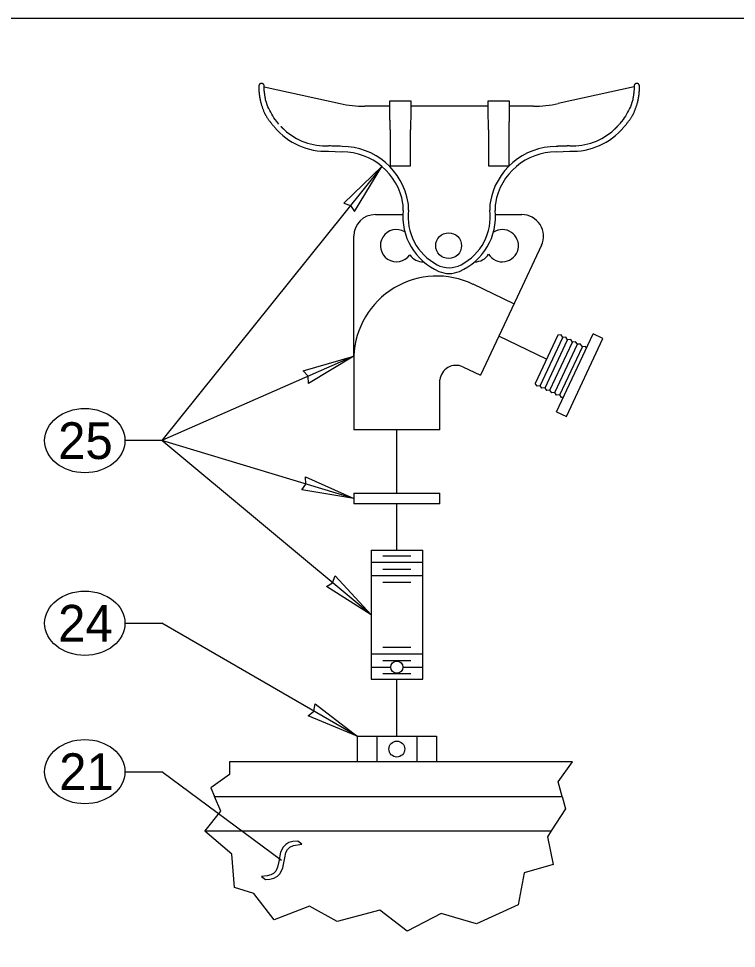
# Model space of a CAD drawing. Extents: x 99862 to 104211, y 98939 to 102076.
# Drawn here: x 100530.8 to 100843.6, y 101670.5 to 102075.5 of the extents above; entities that cross this region are included whole.
import ezdxf

# ---------------------------------------------------------------- set-up
doc = ezdxf.new("R2010")
doc.units = 0
for name, color, linetype in [('Level 1', 7, 'Continuous'), ('Level 15', 7, 'Continuous'), ('Level 17', 7, 'Continuous'), ('Level 18', 7, 'Continuous'), ('Level 2', 7, 'Continuous'), ('Level 20', 7, 'Continuous'), ('Level 22', 7, 'Continuous'), ('Level 25', 7, 'Continuous'), ('Level 26', 7, 'Continuous'), ('Level 27', 7, 'Continuous')]:
    doc.layers.add(name, color=color, linetype=linetype)

msp = doc.modelspace()

# ---------------------------------------------------------------- linework, layer by layer
at = {"layer": 'Level 1'}
msp.add_lwpolyline([(99862, 99999.5), (103151, 99999.5), (103151, 102075.5), (99862, 102075.5)], close=True, dxfattribs=at)
at = {"layer": 'Level 15'}
for p, q in [((100637.87, 102045.83), (100670.91, 102038.49)), ((100799.04, 102045.83), (100766.01, 102038.49)), ((100689.17, 102011.09), (100593.19, 101891.68)), ((100760.94, 101927.13), (100740.1, 101937.17)), ((100676.92, 101928.49), (100593.19, 101891.68)), ((100695.68, 101868.81), (100695.67, 101896.36)), ((100593.19, 101891.68), (100577.19, 101891.68)), ((100684.42, 101815.87), (100593.19, 101891.68)), ((100676.92, 101866.47), (100593.19, 101891.68)), ((100695.69, 101844), (100695.68, 101864.12)), ((100577.19, 101812.14), (100593.19, 101812.14)), ((100678.35, 101762.98), (100593.19, 101812.14)), ((100695.73, 101762.98), (100695.72, 101787.75)), ((100577.19, 101747.5), (100593.19, 101747.5)), ((100645.46, 101708.87), (100593.19, 101747.5)), ((100650.38, 101717.06), (100648.66, 101716.6)), ((100652.52, 101717.18), (100650.38, 101717.06)), ((100654.22, 101715.92), (100652.52, 101717.18)), ((100646.11, 101714.59), (100644.96, 101712.41)), ((100647.26, 101715.8), (100646.11, 101714.59)), ((100648.66, 101716.6), (100647.26, 101715.8)), ((100647.36, 101712.33), (100648.05, 101713.66)), ((100648.05, 101713.66), (100649.08, 101714.64)), ((100649.08, 101714.64), (100650.57, 101715.34)), ((100650.57, 101715.34), (100654.22, 101715.92)), ((100644.96, 101712.41), (100644.24, 101708.38)), ((100646.02, 101705.62), (100646.89, 101709.95)), ((100646.89, 101709.95), (100647.36, 101712.33)), ((100643.73, 101705.89), (100642.9, 101704.16)), ((100644.24, 101708.38), (100643.73, 101705.89)), ((100644.81, 101703.19), (100646.02, 101705.62)), ((100639.1, 101702.09), (100636.69, 101701.85)), ((100636.69, 101701.85), (100638.39, 101700.59)), ((100638.39, 101700.59), (100640.38, 101700.62)), ((100640.78, 101702.53), (100639.1, 101702.09)), ((100640.38, 101700.62), (100642.11, 101701.06)), ((100641.96, 101703.2), (100640.78, 101702.53)), ((100642.9, 101704.16), (100641.96, 101703.2)), ((100642.11, 101701.06), (100643.59, 101701.92)), ((100643.59, 101701.92), (100644.81, 101703.19))]:
    msp.add_line(p, q, dxfattribs=at)
for points in [[(100689.17, 102011.09), (100672.54, 101995.17), (100675.53, 101994.12), (100677.19, 101991.43)], [(100676.92, 101928.49), (100657.22, 101916.57), (100656.99, 101919.73), (100654.82, 101922.04)], [(100676.92, 101866.47), (100654.2, 101870.19), (100656.07, 101872.74), (100655.92, 101875.91)], [(100684.42, 101815.87), (100664.96, 101828.17), (100667.68, 101829.79), (100668.77, 101832.76)], [(100678.35, 101762.98), (100657.09, 101771.81), (100659.5, 101773.86), (100660.07, 101776.98)]]:
    msp.add_lwpolyline(points, close=True, dxfattribs=at)
for centre, start, end in [((100681.76, 102087.3), 257.4712, 270), ((100755.16, 102087.3), 270, 282.5288)]:
    msp.add_arc(centre, 50, start, end, dxfattribs=at)
at = {"layer": 'Level 17'}
for p, q in [((100635.53, 102046.09), (100635.53, 102044.84)), ((100637.87, 102044.84), (100637.87, 102046.09)), ((100799.04, 102046.09), (100799.04, 102044.84)), ((100801.39, 102044.84), (100801.39, 102046.09)), ((100665.92, 102017.72), (100671.76, 102017.51)), ((100765.16, 102017.51), (100770.98, 102017.72))]:
    msp.add_line(p, q, dxfattribs=at)
for centre, radius, start, end in [((100772.09, 102047), 26.95, 317.1843, 319.798), ((100664.84, 102047.03), 29.33, 220.0203, 272.1185), ((100664.82, 102047), 26.97, 227.4639, 272.2359), ((100772.09, 102047), 29.3, 267.8348, 319.9497), ((100772.09, 102047), 26.97, 267.7641, 312.5361), ((100671.71, 101990.56), 29.28, 9.1878, 89.8248), ((100671.71, 101990.56), 26.95, 9.4424, 89.8097), ((100765.2, 101990.56), 29.28, 90.1752, 170.8122), ((100765.2, 101990.56), 26.95, 90.1903, 170.5576), ((100687.2, 101993.13), 11.25, 354.1689, 9.4424), ((100724.32, 101989.34), 23.79, 173.2924, 242.1551), ((100689.51, 101993.44), 11.25, 353.2924, 9.1878), ((100712.6, 101989.34), 23.79, 297.8449, 6.7076), ((100747.4, 101993.44), 11.25, 170.8122, 186.7076), ((100749.71, 101993.13), 11.25, 170.5576, 185.8311), ((100724.32, 101989.34), 26.06, 174.1689, 246.6908), ((100712.6, 101989.34), 26.06, 293.3092, 5.8311), ((100718.46, 101978.25), 11.25, 242.1551, 297.8449), ((100718.46, 101975.74), 11.25, 246.6908, 293.3092)]:
    msp.add_arc(centre, radius, start, end, dxfattribs=at)
for points, degree in [([(100637.87, 102046.09), (100637.87, 102046.13), (100637.87, 102046.17), (100637.87, 102046.2), (100637.85, 102046.33), (100637.82, 102046.46), (100637.76, 102046.58), (100637.71, 102046.7), (100637.63, 102046.81), (100637.54, 102046.91), (100637.45, 102047), (100637.34, 102047.08), (100637.23, 102047.14), (100637.11, 102047.2), (100636.98, 102047.24), (100636.85, 102047.26), (100636.72, 102047.27), (100636.58, 102047.27), (100636.46, 102047.24), (100636.33, 102047.21), (100636.2, 102047.16), (100636.09, 102047.1), (100635.98, 102047.03), (100635.88, 102046.94), (100635.79, 102046.84), (100635.71, 102046.74), (100635.64, 102046.62), (100635.6, 102046.5), (100635.55, 102046.37), (100635.53, 102046.23), (100635.53, 102046.09)], 3), ([(100635.53, 102044.72), (100635.59, 102043.34), (100635.83, 102041.51), (100636.22, 102039.51)], 2), ([(100638.46, 102040.12), (100638.32, 102041.01), (100638.18, 102041.86), (100637.97, 102043.42), (100637.9, 102044.12), (100637.87, 102044.84)], 3), ([(100799.04, 102044.84), (100799.01, 102044.12), (100798.94, 102043.42), (100798.74, 102041.86), (100798.6, 102041.01), (100798.46, 102040.12)], 3), ([(100801.39, 102046.09), (100801.39, 102046.23), (100801.37, 102046.36), (100801.32, 102046.48), (100801.28, 102046.61), (100801.21, 102046.72), (100801.13, 102046.83), (100801.05, 102046.93), (100800.95, 102047.02), (100800.84, 102047.09), (100800.73, 102047.16), (100800.6, 102047.21), (100800.47, 102047.24), (100800.35, 102047.27), (100800.21, 102047.27), (100800.08, 102047.26), (100799.95, 102047.24), (100799.82, 102047.21), (100799.7, 102047.15), (100799.59, 102047.09), (100799.48, 102047.01), (100799.38, 102046.92), (100799.29, 102046.83), (100799.21, 102046.71), (100799.16, 102046.6), (100799.1, 102046.48), (100799.06, 102046.35), (100799.05, 102046.22), (100799.05, 102046.18), (100799.04, 102046.13), (100799.04, 102046.09)], 3), ([(100800.69, 102039.51), (100801.1, 102041.53), (100801.32, 102043.33), (100801.38, 102044.72)], 2), ([(100636.22, 102039.5), (100637.35, 102035.51), (100639.51, 102031.54), (100642.38, 102028.17)], 2), ([(100644.27, 102029.57), (100642.86, 102031.21), (100641.7, 102032.91), (100639.74, 102036.46), (100638.96, 102038.32), (100638.46, 102040.12)], 3), ([(100798.46, 102040.12), (100797.96, 102038.32), (100797.17, 102036.45), (100795.21, 102032.89), (100794.04, 102031.19), (100792.68, 102029.6)], 3), ([(100794.54, 102028.17), (100797.4, 102031.54), (100799.57, 102035.52), (100800.7, 102039.5)], 2), ([(100791.86, 102028.68), (100791.36, 102028.14), (100790.84, 102027.62), (100790.32, 102027.13)], 2), ([(100646.59, 102027.13), (100646.14, 102027.56), (100645.69, 102028.01), (100645.25, 102028.47)], 2), ([(100671.8, 102019.84), (100671.04, 102019.87), (100670.28, 102019.89), (100669.52, 102019.92), (100668.33, 102019.97), (100667.15, 102020.01), (100665.96, 102020.05)], 3), ([(100770.95, 102020.05), (100769.01, 102019.98), (100767.06, 102019.91), (100765.11, 102019.84)], 2)]:
    msp.add_open_spline(points, degree=degree, dxfattribs=at)
at = {"layer": 'Level 18'}
for p, q in [((100758.13, 101915.6), (100767.97, 101936.61)), ((100760.25, 101914.61), (100770.09, 101935.62)), ((100765.28, 101904.17), (100781.19, 101938.13)), ((100767.2, 101937.75), (100765.85, 101937.61)), ((100767.97, 101936.61), (100767.2, 101937.75)), ((100769.33, 101936.75), (100767.97, 101936.61)), ((100770.09, 101935.62), (100769.33, 101936.75)), ((100771.45, 101935.76), (100770.09, 101935.62)), ((100772.21, 101934.63), (100771.45, 101935.76)), ((100762.37, 101913.61), (100772.21, 101934.63)), ((100764.49, 101912.62), (100774.34, 101933.63)), ((100766.67, 101911.63), (100776.49, 101932.59)), ((100773.57, 101934.77), (100772.21, 101934.63)), ((100774.34, 101933.63), (100773.57, 101934.77)), ((100775.69, 101933.77), (100774.34, 101933.63)), ((100776.49, 101932.59), (100775.69, 101933.77)), ((100777.9, 101932.74), (100776.49, 101932.59)), ((100778.35, 101932.07), (100777.9, 101932.74)), ((100756.77, 101915.46), (100756, 101916.6)), ((100758.13, 101915.6), (100756.77, 101915.46)), ((100758.89, 101914.47), (100758.13, 101915.6)), ((100760.25, 101914.61), (100758.89, 101914.47)), ((100761.01, 101913.47), (100760.25, 101914.61)), ((100762.37, 101913.61), (100761.01, 101913.47)), ((100763.13, 101912.48), (100762.37, 101913.61)), ((100764.49, 101912.62), (100763.13, 101912.48)), ((100765.26, 101911.49), (100764.49, 101912.62)), ((100766.67, 101911.63), (100765.26, 101911.49)), ((100767.46, 101910.45), (100766.67, 101911.63)), ((100768.27, 101910.53), (100767.46, 101910.45))]:
    msp.add_line(p, q, dxfattribs=at)
for centre, start, end in [((100695.53, 101976.6), 59.0864, 325.3659), ((100741.62, 101976.6), 211.883, 123.6164), ((100707.1, 101976.6), 214.6341, 271.9878), ((100729.68, 101976.6), 269.1023, 328.117)]:
    msp.add_arc(centre, 7.03, start, end, dxfattribs=at)
at = {"layer": 'Level 2'}
for p, q in [((100676.92, 101868.81), (100714.42, 101868.81)), ((100676.92, 101868.81), (100676.92, 101864.12)), ((100714.42, 101864.12), (100714.42, 101868.81)), ((100714.42, 101864.12), (100676.92, 101864.12))]:
    msp.add_line(p, q, dxfattribs=at)
msp.add_circle((100695.63, 101793.03), 2.65, dxfattribs=at)
at = {"layer": 'Level 20'}
for centre in [(100559.69, 101891.68), (100559.69, 101812.14), (100559.69, 101747.5)]:
    msp.add_ellipse(centre, major_axis=(-17.5, 0), ratio=0.8, dxfattribs=at)
at = {"layer": 'Level 22'}
for p, q in [((100695.67, 101751.73), (100622.7, 101751.73)), ((100622.7, 101751.73), (100622.7, 101746.22)), ((100772.25, 101751.73), (100695.67, 101751.73)), ((100765.94, 101743.12), (100772.25, 101751.73)), ((100622.7, 101746.22), (100614.54, 101740.53)), ((100767.67, 101736.73), (100765.94, 101743.12)), ((100614.54, 101740.53), (100616.19, 101736.73)), ((100618.99, 101730.26), (100616.19, 101736.73)), ((100616.19, 101736.73), (100767.67, 101736.73)), ((100767.67, 101736.73), (100769.15, 101731.25)), ((100612.17, 101721.73), (100618.99, 101730.26)), ((100769.15, 101731.25), (100762.94, 101721.73)), ((100612.06, 101721.6), (100612.17, 101721.73)), ((100623.69, 101711.58), (100612.06, 101721.6)), ((100612.17, 101721.73), (100762.94, 101721.73)), ((100762.94, 101721.73), (100761.24, 101719.13)), ((100761.24, 101719.13), (100763.71, 101707)), ((100624.93, 101697.11), (100623.69, 101711.58)), ((100763.71, 101707), (100751.09, 101703.42)), ((100751.09, 101703.42), (100748.5, 101689.44)), ((100633.34, 101694.39), (100624.93, 101697.11)), ((100642.24, 101683.01), (100633.34, 101694.39)), ((100657.58, 101688.95), (100642.24, 101683.01)), ((100669.7, 101682.27), (100657.58, 101688.95)), ((100748.5, 101689.44), (100730.31, 101681.28)), ((100688.26, 101687.21), (100669.7, 101682.27)), ((100700.13, 101678.06), (100688.26, 101687.21)), ((100714.98, 101685.73), (100700.13, 101678.06)), ((100730.31, 101681.28), (100714.98, 101685.73))]:
    msp.add_line(p, q, dxfattribs=at)
at = {"layer": 'Level 25'}
for p, q in [((100678.35, 101762.98), (100678.35, 101751.73)), ((100678.35, 101762.98), (100687.01, 101762.98)), ((100687.01, 101762.98), (100704.33, 101762.98)), ((100704.33, 101762.98), (100712.99, 101762.98)), ((100712.99, 101762.98), (100712.99, 101751.73))]:
    msp.add_line(p, q, dxfattribs=at)
at = {"layer": 'Level 26'}
for p, q in [((100692.5, 102037.3), (100681.76, 102037.3)), ((100692.5, 102039.47), (100692.5, 102032.46)), ((100701.87, 102039.47), (100692.5, 102039.47)), ((100701.87, 102032.46), (100701.87, 102039.47)), ((100735.37, 102037.3), (100701.87, 102037.3)), ((100744.75, 102039.47), (100735.37, 102039.47)), ((100735.37, 102039.47), (100735.37, 102032.47)), ((100744.75, 102032.45), (100744.75, 102039.47)), ((100755.16, 102037.3), (100744.75, 102037.3)), ((100692.7, 102027.09), (100692.7, 102011.34)), ((100701.67, 102011.34), (100701.67, 102027.09)), ((100735.57, 102027.09), (100735.57, 102011.34)), ((100744.54, 102011.34), (100744.54, 102027.09)), ((100692.7, 102011.34), (100701.67, 102011.34)), ((100735.57, 102011.34), (100744.54, 102011.34)), ((100686.3, 101990.12), (100698.27, 101990.12)), ((100738.64, 101990.12), (100750.16, 101990.12)), ((100676.92, 101928.49), (100676.92, 101980.74)), ((100758.65, 101976.76), (100748.06, 101954.15)), ((100746.67, 101951.2), (100728.93, 101959.76)), ((100748.06, 101954.15), (100732.15, 101920.19)), ((100765.85, 101937.61), (100756, 101916.6)), ((100769.53, 101902.18), (100785.43, 101936.14)), ((100785.43, 101936.14), (100781.19, 101938.13)), ((100676.92, 101928.49), (100676.92, 101896.36)), ((100724.4, 101923.82), (100732.15, 101920.19)), ((100714.42, 101896.36), (100714.42, 101918.14)), ((100765.28, 101904.17), (100769.53, 101902.18)), ((100714.42, 101896.36), (100676.92, 101896.36)), ((100684.42, 101844), (100706.92, 101844)), ((100684.42, 101844), (100684.42, 101787.75)), ((100706.92, 101787.75), (100706.92, 101844)), ((100684.42, 101787.75), (100706.92, 101787.75))]:
    msp.add_line(p, q, dxfattribs=at)
msp.add_circle((100718.23, 101976.6), 5.63, dxfattribs=at)
for centre, radius, start, end in [((100686.3, 101980.74), 9.38, 90, 180), ((100750.16, 101980.74), 9.38, 334.9044, 90), ((100713.16, 101927.11), 36.26, 64.2104, 177.8152), ((100721.42, 101917.45), 7.03, 64.9044, 174.3501)]:
    msp.add_arc(centre, radius, start, end, dxfattribs=at)
for points in [[(100735.37, 102032.67), (100735.36, 102032.04), (100735.4, 102031.36), (100735.49, 102029.51), (100735.54, 102028.28), (100735.51, 102027.09)], [(100744.61, 102027.09), (100744.58, 102028.29), (100744.63, 102029.51), (100744.72, 102031.37), (100744.76, 102032.06), (100744.75, 102032.69)], [(100692.5, 102032.55), (100692.5, 102032.48), (100692.5, 102032.41), (100692.5, 102031.8), (100692.53, 102031.25), (100692.62, 102029.51), (100692.66, 102028.3), (100692.64, 102027.09)], [(100701.73, 102027.09), (100701.71, 102028.3), (100701.75, 102029.5), (100701.84, 102031.23), (100701.87, 102031.79), (100701.87, 102032.37), (100701.87, 102032.42), (100701.87, 102032.47)]]:
    msp.add_open_spline(points, degree=3, dxfattribs=at)
at = {"layer": 'Level 27'}
for p, q in [((100684.38, 101838.72), (100706.88, 101838.72)), ((100689.55, 101841.51), (100701.8, 101841.51)), ((100689.55, 101835.76), (100701.8, 101835.76)), ((100684.38, 101832.97), (100706.88, 101832.97)), ((100689.55, 101830.08), (100701.8, 101830.08)), ((100684.38, 101798.77), (100706.88, 101798.77)), ((100689.55, 101801.67), (100701.8, 101801.67)), ((100689.55, 101795.98), (100701.8, 101795.98)), ((100684.38, 101793.03), (100692.99, 101793.03)), ((100689.55, 101790.24), (100701.8, 101790.24)), ((100698.28, 101793.03), (100706.88, 101793.03)), ((100687.01, 101762.98), (100687.01, 101751.73)), ((100704.33, 101762.98), (100704.33, 101751.73))]:
    msp.add_line(p, q, dxfattribs=at)
msp.add_circle((100695.67, 101757.35), 3.46, dxfattribs=at)

# ---------------------------------------------------------------- texts
at = {"layer": 'Level 20'}
for s, p in [('25', (100548.06, 101883.68)), ('24', (100548.06, 101804.14)), ('21', (100548.52, 101739.5))]:
    msp.add_text(s, height=16, dxfattribs=at).set_placement(p)

doc.saveas('drawing.dxf')
